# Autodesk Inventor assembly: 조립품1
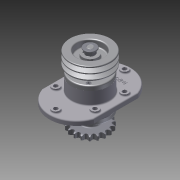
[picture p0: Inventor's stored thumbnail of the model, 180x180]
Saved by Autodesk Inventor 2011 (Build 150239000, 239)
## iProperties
Created: 2015-02
Part Number: 조립품1
Document SubType Name: Assembly
Designer: Administrator
Author: Administrator
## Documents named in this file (11)
- C:\Documents and Settings\Administrator\바탕 화면\조립품1.iam
- C:\Documents and Settings\Administrator\바탕 화면\본체.ipt
- C:\Documents and Settings\Administrator\바탕 화면\450207V1009\3-축.ipt
- C:\Documents and Settings\Administrator\바탕 화면\450207V1009\11-키 6x6.ipt
- C:\Documents and Settings\Administrator\바탕 화면\450207V1009\4-V벨트풀리.ipt
- C:\Documents and Settings\Administrator\바탕 화면\450207V1009\9-M16-너트.ipt
- C:\Documents and Settings\Administrator\바탕 화면\450207V1009\2-커버.ipt
- C:\Documents and Settings\Administrator\바탕 화면\450207V1009\6-베어링 6206.ipt
- C:\Documents and Settings\Administrator\바탕 화면\450207V1009\8-오일실 30x42.ipt
- C:\Documents and Settings\Administrator\바탕 화면\450207V1009\10-M6.ipt
- C:\Documents and Settings\Administrator\바탕 화면\450207V1009\5-체인 스프로킷.ipt
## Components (21 placed, 9 different names)
1. 3-축:1
2. 11-키 6x6:1 — 각도:1, 각도:7
3. 4-V벨트풀리:1 — 각도:1
4. 9-M16 너트:1 — 각도:2
5. 2-커버:1
6. 6-베어링 6206:1
7. 6-베어링 6206:2
8. 2-커버:2
9. 8-8-오일실 30x42:1
10. 8-8-오일실 30x42:2
11. 5-체인 스프로킷:1
12. 11-키 6x6:2 — 각도:7
13. 9-M16 너트:2 — 각도:6
14. 10-M6:1 — 각도:3
15. 10-M6:3
16. 10-M6:4
17. 10-M6:5
18. 10-M6:2 — 각도:4
19. 10-M6:6
20. 10-M6:7
21. 10-M6:8
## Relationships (6: Angle 6)
- 각도:1 [Angle]: 11-키 6x6:1 ↔ 4-V벨트풀리:1
- 각도:2 [Angle]: 9-M16 너트:1
- 각도:3 [Angle]: 10-M6:1
- 각도:4 [Angle]: 10-M6:2
- 각도:6 [Angle]: 9-M16 너트:2
- 각도:7 [Angle]: 11-키 6x6:1 ↔ 11-키 6x6:2
